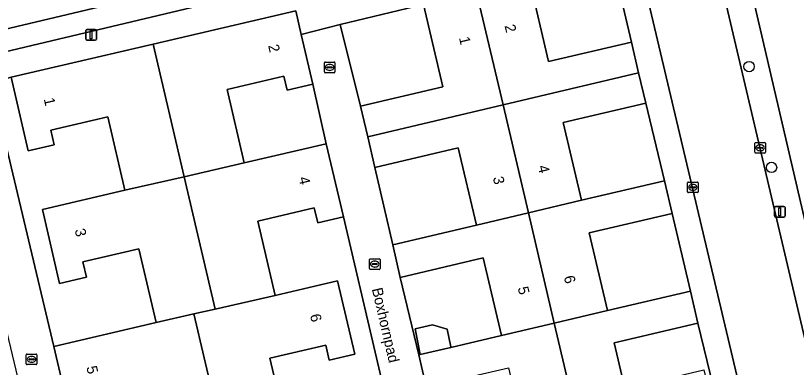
# Model space of a CAD drawing. Extents: x 162989 to 165008, y 383432 to 384338.
# Drawn here: x 164168.7 to 164242.3, y 384078.9 to 384112.1 of the extents above; entities that cross this region are included whole.
import ezdxf

# ---------------------------------------------------------------- set-up
doc = ezdxf.new("R2010")
doc.units = 0
for name, color, linetype in [('IMGEO_Boom', 7, 'Continuous'), ('IMGEO_Erf', 7, 'Continuous'), ('IMGEO_Kolk', 7, 'Continuous'), ('IMGEO_Lichtmast', 7, 'Continuous'), ('IMGEO_Muur', 7, 'Continuous'), ('IMGEO_Openbare_ruimte_label', 7, 'Continuous'), ('IMGEO_Pand', 7, 'Continuous'), ('IMGEO_Pand_nummerreeks', 7, 'Continuous'), ('IMGEO_Parkeervlak_open', 7, 'Continuous'), ('IMGEO_Rijbaan_lokaal_open', 7, 'Continuous'), ('IMGEO_Voetpad_open', 7, 'Continuous')]:
    doc.layers.add(name, color=color, linetype=linetype)

msp = doc.modelspace()

# ---------------------------------------------------------------- linework, layer by layer
at = {"layer": 'IMGEO_Boom'}
for centre in [(164237.799, 384107.27), (164239.915, 384097.775)]:
    msp.add_circle(centre, 0.489, dxfattribs=at)
at = {"layer": 'IMGEO_Erf'}
for points in [[(164237.197, 384117.905), (164237.578, 384116.269), (164244.582, 384086.161), (164264.403, 384091.019), (164264.201, 384093.07), (164261.204, 384092.933), (164259.932, 384120.17)], [(164208.559, 384054.87), (164199.592, 384093.127), (164197.172, 384092.562), (164196.846, 384093.957), (164191.533, 384092.714), (164193.172, 384085.708), (164199.053, 384087.084), (164200.668, 384080.179), (164198.265, 384079.617), (164197.938, 384081.015), (164192.672, 384079.784), (164194.291, 384072.86)]]:
    msp.add_lwpolyline(points, dxfattribs=at)
for points in [[(164224.863, 384117.452), (164217.12, 384115.455), (164218.924, 384107.739), (164226.726, 384109.563)], [(164201.215, 384103.551), (164208.963, 384105.363), (164207.147, 384113.123), (164199.299, 384111.227)], [(164172.337, 384080.9), (164181.966, 384083.155), (164180.341, 384090.107), (164175.057, 384088.871), (164175.393, 384087.436), (164172.871, 384086.846), (164171.246, 384093.799), (164179.021, 384095.617), (164177.401, 384102.545), (164172.03, 384101.289), (164172.353, 384099.909), (164169.919, 384099.339), (164168.302, 384106.258), (164166.404, 384105.745), (164166.968, 384103.385)], [(164196.718, 384105.611), (164194.3, 384105.045), (164193.993, 384106.357), (164188.647, 384105.107), (164190.263, 384098.196), (164197.984, 384100.002)], [(164228.069, 384103.819), (164220.302, 384102.003), (164222.013, 384094.686), (164229.838, 384096.516)], [(164204.24, 384090.47), (164212.121, 384092.315), (164210.415, 384099.608), (164202.566, 384097.772)], [(164230.56, 384093.427), (164222.747, 384091.6), (164224.457, 384084.29), (164232.276, 384086.118)], [(164212.761, 384089.237), (164204.955, 384087.411), (164206.691, 384080.11), (164206.826, 384080.141), (164206.355, 384082.555), (164207.988, 384082.933), (164209.375, 384082.518), (164209.7, 384080.851), (164209.704, 384080.815), (164214.47, 384081.93)], [(164234.232, 384075.753), (164234.722, 384075.868), (164232.983, 384083.096), (164225.106, 384081.254), (164226.799, 384074.016), (164231.186, 384075.041), (164230.529, 384077.769), (164230.48, 384077.976), (164233.545, 384078.692)]]:
    msp.add_lwpolyline(points, close=True, dxfattribs=at)
at = {"layer": 'IMGEO_Kolk'}
for p, q in [((164197.8, 384106.768), (164197.8, 384107.62)), ((164197.875, 384107.694), (164198.727, 384107.694)), ((164198.288, 384107.474), (164198.313, 384107.474)), ((164198.801, 384107.62), (164198.801, 384106.768)), ((164198.059, 384107.188), (164198.059, 384107.2)), ((164198.497, 384107.151), (164198.099, 384107.151)), ((164198.102, 384107.237), (164198.5, 384107.237)), ((164198.311, 384106.914), (164198.286, 384106.914)), ((164198.543, 384107.2), (164198.543, 384107.188)), ((164198.727, 384106.694), (164197.875, 384106.694)), ((164238.413, 384100.118), (164239.265, 384100.118)), ((164238.338, 384099.192), (164238.338, 384100.044)), ((164238.597, 384099.612), (164238.597, 384099.624)), ((164239.035, 384099.575), (164238.637, 384099.575)), ((164238.64, 384099.661), (164239.038, 384099.661)), ((164238.826, 384099.898), (164238.851, 384099.898)), ((164239.081, 384099.624), (164239.081, 384099.612)), ((164239.339, 384100.044), (164239.339, 384099.192)), ((164239.265, 384099.118), (164238.413, 384099.118)), ((164238.849, 384099.338), (164238.824, 384099.338)), ((164232.006, 384095.468), (164232.006, 384096.32)), ((164232.081, 384096.394), (164232.933, 384096.394)), ((164232.265, 384095.888), (164232.265, 384095.9)), ((164232.703, 384095.851), (164232.305, 384095.851)), ((164232.308, 384095.937), (164232.706, 384095.937)), ((164232.494, 384096.174), (164232.519, 384096.174)), ((164232.749, 384095.9), (164232.749, 384095.888)), ((164233.007, 384096.32), (164233.007, 384095.468)), ((164232.933, 384095.394), (164232.081, 384095.394)), ((164232.517, 384095.614), (164232.492, 384095.614)), ((164202.047, 384088.236), (164202.047, 384089.088)), ((164202.122, 384089.162), (164202.974, 384089.162)), ((164203.048, 384089.088), (164203.048, 384088.236)), ((164202.306, 384088.656), (164202.306, 384088.668)), ((164202.744, 384088.619), (164202.346, 384088.619)), ((164202.349, 384088.705), (164202.747, 384088.705)), ((164202.558, 384088.382), (164202.533, 384088.382)), ((164202.535, 384088.942), (164202.56, 384088.942)), ((164202.79, 384088.668), (164202.79, 384088.656)), ((164202.974, 384088.162), (164202.122, 384088.162)), ((164169.727, 384079.262), (164169.727, 384080.114)), ((164169.802, 384080.188), (164170.654, 384080.188)), ((164169.986, 384079.682), (164169.986, 384079.694)), ((164170.424, 384079.645), (164170.026, 384079.645)), ((164170.029, 384079.731), (164170.427, 384079.731)), ((164170.215, 384079.968), (164170.24, 384079.968)), ((164170.47, 384079.694), (164170.47, 384079.682)), ((164170.728, 384080.114), (164170.728, 384079.262)), ((164170.654, 384079.188), (164169.802, 384079.188)), ((164170.238, 384079.408), (164170.213, 384079.408))]:
    msp.add_line(p, q, dxfattribs=at)
for points in [[(164197.8, 384106.768), (164197.8, 384107.62)], [(164197.875, 384107.694), (164198.727, 384107.694)], [(164198.801, 384107.62), (164198.801, 384106.768)], [(164198.727, 384106.694), (164197.875, 384106.694)], [(164238.413, 384100.118), (164239.265, 384100.118)], [(164238.338, 384099.192), (164238.338, 384100.044)], [(164239.339, 384100.044), (164239.339, 384099.192)], [(164239.265, 384099.118), (164238.413, 384099.118)], [(164232.006, 384095.468), (164232.006, 384096.32)], [(164232.081, 384096.394), (164232.933, 384096.394)], [(164233.007, 384096.32), (164233.007, 384095.468)], [(164232.933, 384095.394), (164232.081, 384095.394)], [(164202.047, 384088.236), (164202.047, 384089.088)], [(164202.122, 384089.162), (164202.974, 384089.162)], [(164203.048, 384089.088), (164203.048, 384088.236)], [(164202.974, 384088.162), (164202.122, 384088.162)], [(164169.727, 384079.262), (164169.727, 384080.114)], [(164169.802, 384080.188), (164170.654, 384080.188)], [(164170.728, 384080.114), (164170.728, 384079.262)], [(164170.654, 384079.188), (164169.802, 384079.188)]]:
    msp.add_lwpolyline(points, dxfattribs=at)
for centre, radius, start, end in [((164197.877, 384107.618), 0.0765, 91.55205, 178.44795), ((164197.877, 384107.618), 0.0765, 91.55205, 178.44795), ((164198.725, 384107.618), 0.0765, 1.55205, 88.44795), ((164198.725, 384107.618), 0.0765, 1.55205, 88.44795), ((164197.877, 384106.77), 0.0765, 181.55205, 268.44795), ((164197.877, 384106.77), 0.0765, 181.55205, 268.44795), ((164198.099, 384107.197), 0.0403, 85.87752, 175.75265), ((164198.096, 384107.187), 0.0366, 178.93798, 274.71019), ((164198.5, 384107.194), 0.043, 264.86636, 352.45326), ((164198.504, 384107.199), 0.0386, 1.73085, 96.63898), ((164198.725, 384106.77), 0.0765, 271.55205, 358.44795), ((164198.725, 384106.77), 0.0765, 271.55205, 358.44795), ((164238.415, 384100.042), 0.0765, 91.55205, 178.44795), ((164238.415, 384100.042), 0.0765, 91.55205, 178.44795), ((164239.263, 384100.042), 0.0765, 1.55205, 88.44795), ((164239.263, 384100.042), 0.0765, 1.55205, 88.44795), ((164238.637, 384099.621), 0.0403, 85.87752, 175.75265), ((164238.634, 384099.611), 0.0366, 178.93798, 274.71019), ((164239.038, 384099.618), 0.043, 264.86636, 352.45326), ((164239.042, 384099.623), 0.0386, 1.73085, 96.63898), ((164238.415, 384099.194), 0.0765, 181.55205, 268.44795), ((164238.415, 384099.194), 0.0765, 181.55205, 268.44795), ((164239.263, 384099.194), 0.0765, 271.55205, 358.44795), ((164239.263, 384099.194), 0.0765, 271.55205, 358.44795), ((164232.083, 384096.318), 0.0765, 91.55205, 178.44795), ((164232.083, 384096.318), 0.0765, 91.55205, 178.44795), ((164232.305, 384095.897), 0.0403, 85.87752, 175.75265), ((164232.302, 384095.887), 0.0366, 178.93798, 274.71019), ((164232.706, 384095.894), 0.043, 264.86636, 352.45326), ((164232.71, 384095.899), 0.0386, 1.73085, 96.63898), ((164232.931, 384096.318), 0.0765, 1.55205, 88.44795), ((164232.931, 384096.318), 0.0765, 1.55205, 88.44795), ((164232.083, 384095.47), 0.0765, 181.55205, 268.44795), ((164232.083, 384095.47), 0.0765, 181.55205, 268.44795), ((164232.931, 384095.47), 0.0765, 271.55205, 358.44795), ((164232.931, 384095.47), 0.0765, 271.55205, 358.44795), ((164202.124, 384089.086), 0.0765, 91.55205, 178.44795), ((164202.124, 384089.086), 0.0765, 91.55205, 178.44795), ((164202.972, 384089.086), 0.0765, 1.55205, 88.44795), ((164202.972, 384089.086), 0.0765, 1.55205, 88.44795), ((164202.346, 384088.665), 0.0403, 85.87752, 175.75265), ((164202.343, 384088.655), 0.0366, 178.93798, 274.71019), ((164202.747, 384088.662), 0.043, 264.86636, 352.45326), ((164202.751, 384088.667), 0.0386, 1.73085, 96.63898), ((164202.124, 384088.238), 0.0765, 181.55205, 268.44795), ((164202.124, 384088.238), 0.0765, 181.55205, 268.44795), ((164202.972, 384088.238), 0.0765, 271.55205, 358.44795), ((164202.972, 384088.238), 0.0765, 271.55205, 358.44795), ((164169.804, 384080.112), 0.0765, 91.55205, 178.44795), ((164169.804, 384080.112), 0.0765, 91.55205, 178.44795), ((164170.026, 384079.691), 0.0403, 85.87752, 175.75265), ((164170.023, 384079.681), 0.0366, 178.93798, 274.71019), ((164170.427, 384079.688), 0.043, 264.86636, 352.45326), ((164170.431, 384079.693), 0.0386, 1.73085, 96.63898), ((164170.652, 384080.112), 0.0765, 1.55205, 88.44795), ((164170.652, 384080.112), 0.0765, 1.55205, 88.44795), ((164169.804, 384079.264), 0.0765, 181.55205, 268.44795), ((164169.804, 384079.264), 0.0765, 181.55205, 268.44795), ((164170.652, 384079.264), 0.0765, 271.55205, 358.44795), ((164170.652, 384079.264), 0.0765, 271.55205, 358.44795)]:
    msp.add_arc(centre, radius, start, end, dxfattribs=at)
for centre, major_axis, ratio, start_param, end_param in [((164198.287, 384107.194), (-0.387, 0.002), 0.722429, 4.712389, 7.853982), ((164198.312, 384107.194), (-0.39, 0.002), 0.717154, 1.570796, 4.712389), ((164238.825, 384099.618), (-0.387, 0.002), 0.722429, 4.712389, 7.853982), ((164238.85, 384099.618), (-0.39, 0.002), 0.717154, 1.570796, 4.712389), ((164232.493, 384095.894), (-0.387, 0.002), 0.722429, 4.712389, 7.853982), ((164232.518, 384095.894), (-0.39, 0.002), 0.717154, 1.570796, 4.712389), ((164202.534, 384088.662), (-0.387, 0.002), 0.722429, 4.712389, 7.853982), ((164202.559, 384088.662), (-0.39, 0.002), 0.717154, 1.570796, 4.712389), ((164170.214, 384079.688), (-0.387, 0.002), 0.722429, 4.712389, 7.853982), ((164170.239, 384079.688), (-0.39, 0.002), 0.717154, 1.570796, 4.712389)]:
    msp.add_ellipse(centre, major_axis=major_axis, ratio=ratio, start_param=start_param, end_param=end_param, dxfattribs=at)
at = {"layer": 'IMGEO_Lichtmast'}
for p, q in [((164175.337, 384109.866), (164175.337, 384110.666)), ((164175.337, 384110.666), (164175.337, 384109.866)), ((164175.437, 384110.766), (164176.227, 384110.766)), ((164176.227, 384110.766), (164175.437, 384110.766)), ((164176.327, 384110.666), (164176.327, 384109.866)), ((164176.327, 384109.866), (164176.327, 384110.666)), ((164176.227, 384109.766), (164175.437, 384109.766)), ((164175.437, 384109.766), (164176.227, 384109.766)), ((164240.197, 384093.194), (164240.197, 384093.994)), ((164240.197, 384093.994), (164240.197, 384093.194)), ((164240.297, 384094.094), (164241.087, 384094.094)), ((164241.087, 384094.094), (164240.297, 384094.094)), ((164241.187, 384093.994), (164241.187, 384093.194)), ((164241.187, 384093.194), (164241.187, 384093.994)), ((164241.087, 384093.094), (164240.297, 384093.094)), ((164240.297, 384093.094), (164241.087, 384093.094))]:
    msp.add_line(p, q, dxfattribs=at)
for points in [[(164175.757, 384110.641), (164175.907, 384110.641), (164175.907, 384109.891), (164175.757, 384109.891), (164175.757, 384110.641)], [(164240.617, 384093.969), (164240.767, 384093.969), (164240.767, 384093.219), (164240.617, 384093.219), (164240.617, 384093.969)]]:
    msp.add_lwpolyline(points, dxfattribs=at)
for centre, start, end in [((164175.437, 384110.666), 90, 180), ((164175.437, 384110.666), 90, 180), ((164176.227, 384110.666), 0, 90), ((164176.227, 384110.666), 360, 90), ((164175.437, 384109.866), 180, 270), ((164175.437, 384109.866), 180, 270), ((164176.227, 384109.866), 270, 0), ((164176.227, 384109.866), 270, 0), ((164240.297, 384093.994), 90, 180), ((164240.297, 384093.994), 90, 180), ((164241.087, 384093.994), 0, 90), ((164241.087, 384093.994), 360, 90), ((164240.297, 384093.194), 180, 270), ((164240.297, 384093.194), 180, 270), ((164241.087, 384093.194), 270, 0), ((164241.087, 384093.194), 270, 0)]:
    msp.add_arc(centre, 0.1, start, end, dxfattribs=at)
at = {"layer": 'IMGEO_Muur'}
for points in [[(164204.955, 384087.411), (164206.691, 384080.11)], [(164232.983, 384083.096), (164234.722, 384075.868)]]:
    msp.add_lwpolyline(points, dxfattribs=at)
at = {"layer": 'IMGEO_Pand'}
for points in [[(164212.132, 384114.289), (164214.626, 384103.672), (164227.397, 384106.692), (164226.726, 384109.563), (164218.924, 384107.739), (164217.12, 384115.455)], [(164201.891, 384100.66), (164214.626, 384103.672), (164212.132, 384114.289), (164207.147, 384113.123), (164208.963, 384105.363), (164201.215, 384103.551)], [(164190.263, 384098.196), (164188.647, 384105.107), (164193.993, 384106.357), (164194.3, 384105.045), (164196.718, 384105.611), (164195.623, 384110.292), (164195.101, 384112.525), (164181.683, 384109.387), (164184.598, 384096.895)], [(164179.021, 384095.617), (164184.598, 384096.895), (164181.683, 384109.387), (164168.302, 384106.258), (164169.919, 384099.339), (164172.353, 384099.909), (164172.03, 384101.289), (164177.401, 384102.545)], [(164217.018, 384093.488), (164222.013, 384094.686), (164220.302, 384102.003), (164228.069, 384103.819), (164227.397, 384106.692), (164214.626, 384103.672)], [(164217.018, 384093.488), (164214.626, 384103.672), (164201.891, 384100.66), (164202.566, 384097.772), (164210.415, 384099.608), (164212.121, 384092.315)], [(164193.172, 384085.708), (164191.533, 384092.714), (164196.846, 384093.957), (164197.172, 384092.562), (164199.592, 384093.127), (164197.984, 384100.002), (164190.263, 384098.196), (164184.598, 384096.895), (164187.508, 384084.419)], [(164187.508, 384084.419), (164184.598, 384096.895), (164179.021, 384095.617), (164171.246, 384093.799), (164172.871, 384086.846), (164175.393, 384087.436), (164175.057, 384088.871), (164180.341, 384090.107), (164181.966, 384083.155), (164185.516, 384083.965)], [(164217.018, 384093.488), (164219.456, 384083.108), (164224.457, 384084.29), (164222.747, 384091.6), (164230.56, 384093.427), (164229.838, 384096.516), (164222.013, 384094.686)], [(164217.018, 384093.488), (164212.121, 384092.315), (164204.24, 384090.47), (164204.955, 384087.411), (164212.761, 384089.237), (164214.47, 384081.93), (164219.456, 384083.108)], [(164193.172, 384085.708), (164187.508, 384084.419), (164185.516, 384083.965), (164188.442, 384071.542), (164194.291, 384072.86), (164192.672, 384079.784), (164197.938, 384081.015), (164198.265, 384079.617), (164200.668, 384080.179), (164199.053, 384087.084)], [(164219.456, 384083.108), (164221.866, 384072.847), (164226.799, 384074.016), (164225.106, 384081.254), (164232.983, 384083.096), (164232.276, 384086.118), (164224.457, 384084.29)], [(164188.442, 384071.542), (164185.516, 384083.965), (164181.966, 384083.155), (164172.337, 384080.9), (164173.967, 384073.93), (164176.41, 384074.501), (164176.085, 384075.89), (164181.464, 384077.148), (164183.059, 384070.33)], [(164209.375, 384082.518), (164207.988, 384082.933), (164206.355, 384082.555), (164206.826, 384080.141), (164209.704, 384080.815), (164209.7, 384080.851)], [(164219.456, 384083.108), (164214.47, 384081.93), (164209.704, 384080.815), (164206.826, 384080.141), (164206.691, 384080.11), (164207.399, 384077.083), (164215.156, 384078.897), (164216.849, 384071.66), (164221.866, 384072.847)]]:
    msp.add_lwpolyline(points, close=True, dxfattribs=at)
at = {"layer": 'IMGEO_Parkeervlak_open'}
for points in [[(164217.91, 384122.702), (164213.897, 384121.749), (164153.186, 384107.334), (164148.372, 384106.191), (164143.674, 384105.076), (164111.13, 384097.35), (164079.752, 384089.901)], [(164083.09, 384088.781), (164111.601, 384095.448), (164144.005, 384103.025), (164157.009, 384106.119), (164214.8, 384119.856)]]:
    msp.add_lwpolyline(points, dxfattribs=at)
at = {"layer": 'IMGEO_Rijbaan_lokaal_open'}
msp.add_lwpolyline([(164146.729, 384112.921), (164148.372, 384106.191), (164153.186, 384107.334), (164213.897, 384121.749), (164212.318, 384128.435), (164152.758, 384114.345), (164151.947, 384114.156), (164150.952, 384113.919)], close=True, dxfattribs=at)
for points in [[(164227.517, 384116.826), (164236.928, 384076.981), (164241.962, 384056.296)], [(164236.086, 384046.718), (164227.391, 384044.691), (164228.984, 384037.862), (164252.072, 384043.378), (164249.058, 384056.151), (164247.449, 384062.968), (164245.302, 384072.068), (164243.675, 384078.963), (164235.037, 384115.701)]]:
    msp.add_lwpolyline(points, dxfattribs=at)
at = {"layer": 'IMGEO_Voetpad_open'}
for points in [[(164214.8, 384119.856), (164157.009, 384106.119), (164144.005, 384103.025), (164111.601, 384095.448), (164083.09, 384088.781)], [(164166.404, 384105.745), (164168.302, 384106.258), (164181.683, 384109.387), (164195.101, 384112.525), (164195.623, 384110.292), (164199.299, 384111.227), (164207.147, 384113.123), (164212.132, 384114.289), (164217.12, 384115.455), (164224.863, 384117.452), (164227.517, 384116.826)], [(164227.517, 384116.826), (164224.863, 384117.452), (164226.726, 384109.563), (164227.397, 384106.692), (164228.069, 384103.819), (164229.838, 384096.516), (164230.56, 384093.427), (164232.276, 384086.118), (164232.983, 384083.096), (164234.722, 384075.868), (164235.434, 384072.823), (164237.142, 384065.554), (164237.841, 384062.563), (164239.71, 384054.876), (164240.241, 384052.672), (164242.094, 384053.217)], [(164241.962, 384056.296), (164236.928, 384076.981), (164227.517, 384116.826)]]:
    msp.add_lwpolyline(points, dxfattribs=at)
for points in [[(164244.582, 384086.161), (164237.578, 384116.269), (164235.037, 384115.701), (164243.675, 384078.963), (164244.157, 384079.078), (164246.112, 384079.596), (164246.598, 384079.712), (164245.85, 384083.21)], [(164206.691, 384080.11), (164204.955, 384087.411), (164204.24, 384090.47), (164202.566, 384097.772), (164201.891, 384100.66), (164201.215, 384103.551), (164199.299, 384111.227), (164195.623, 384110.292), (164196.718, 384105.611), (164197.984, 384100.002), (164199.592, 384093.127), (164208.559, 384054.87), (164209.723, 384049.905), (164210.224, 384047.764), (164210.751, 384045.51), (164214.564, 384046.396), (164214.016, 384048.792), (164212.246, 384056.534), (164211.531, 384059.588), (164209.794, 384066.804), (164209.083, 384069.843), (164207.399, 384077.083)], [(164173.967, 384073.93), (164172.337, 384080.9), (164166.968, 384103.385), (164163.242, 384102.519), (164164.952, 384094.916), (164165.651, 384091.927), (164167.35, 384084.555), (164168.048, 384081.568), (164169.826, 384074.215), (164170.529, 384071.206), (164172.21, 384063.981), (164172.928, 384060.907), (164174.66, 384053.664), (164175.328, 384050.805), (164175.996, 384047.946), (164178.35, 384037.909), (164182.332, 384038.711), (164181.273, 384043.236), (164179.806, 384049.06), (164178.18, 384056.012), (164176.898, 384061.524), (164175.266, 384068.505)]]:
    msp.add_lwpolyline(points, close=True, dxfattribs=at)

# ---------------------------------------------------------------- texts
at = {"layer": 'IMGEO_Openbare_ruimte_label'}
msp.add_text('Boxhornpad', height=1, rotation=283.0075, dxfattribs=at).set_placement((164202.27, 384086.315))
at = {"layer": 'IMGEO_Pand_nummerreeks'}
for s, rotation, p in [('2', 283.15937, (164214.765, 384111.121)), ('1', 283.17136, (164210.472, 384109.975)), ('2', 283.16336, (164192.499, 384109.247)), ('1', 283.15418, (164171.366, 384104.22)), ('4', 283.1615, (164217.902, 384097.866)), ('4', 283.16432, (164195.369, 384096.784)), ('3', 283.16257, (164213.66, 384096.803)), ('3', 283.1546, (164174.283, 384091.882)), ('6', 283.16623, (164220.346, 384087.466)), ('5', 283.16227, (164216.007, 384086.425)), ('6', 283.16418, (164196.441, 384083.852)), ('5', 283.1626, (164175.381, 384078.952))]:
    msp.add_text(s, height=1, rotation=rotation, dxfattribs=at).set_placement(p)

doc.saveas('drawing.dxf')
